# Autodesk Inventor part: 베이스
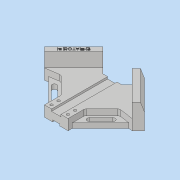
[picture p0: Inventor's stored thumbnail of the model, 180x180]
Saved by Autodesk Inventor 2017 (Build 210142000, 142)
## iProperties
Part Number: 베이스
Material: 일반
Document SubType Name: Modeling
Designer: 00-00
Density: 1 g/cm^3
Appearance: 기본값
Author: 00-00
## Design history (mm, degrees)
sketch "스케치1"
  geometry: L1 (0, 84.853)-(84.853, 0); L2 (84.853, 0)-(0, -84.853); L3 (0, -84.853)-(-84.853, 0); L4 (-84.853, 0)-(0, 84.853); L5 (0, 84.853)-(0, -84.853); L6 (84.853, 0)-(-84.853, 0); L7 (0, 84.853)-(120, 84.853); 1 further point
  constraints: 14 end point, 2 midpoint, 2 parallel, 1 equal length, 1 horizontal, 1 perpendicular
  dimensions: "d0" = 120 distance of L1.start L1.end; "d1" = 45 deg angle of L1 L7; "d2" = 120 distance of L1.end L2.end
extrude "돌출1" new body sketch "스케치1" distance "d3" = 42; taper "d4" = 0 deg
sketch "스케치2"
  geometry: L1 (0, 84.853)-(-84.853, 0) reference; L2 (84.853, 0)-(0, 84.853) reference; L3 (-74.246, -10.607)-(0, 63.64); L4 (0, 63.64)-(74.246, -10.607); L5 (-84.853, 0)-(0, -84.853) reference; L6 (0, -84.853)-(84.853, 0) reference; L7 (-74.246, -10.607)-(0, -84.853); L8 (74.246, -10.607)-(0, -84.853); 1 further point
  constraints: 8 end point, 1 collinear, 1 perpendicular, 1 other
  dimensions: "d5" = 15 distance between parallel lines of L1 L3
extrude "돌출2" cut sketch "스케치2" distance "d6" = 24; taper "d7" = 0 deg
sketch "스케치3"
  geometry: L1 (-20, -64.853)-(20, -64.853); L2 (74.246, -10.607)-(0, -84.853) reference; L3 (0, -84.853)-(-74.246, -10.607) reference; 1 further point
  constraints: 2 end point, 2 point on line, 1 horizontal
  dimensions: "d8" = 20 distance from line of L2.end L1
extrude "돌출3" cut sketch "스케치3" stored distance "d9" = 24; taper "d10" = 0 deg
sketch "스케치4"
  geometry: L1 (-35.355, 49.497)-(-16.005, 30.147); L2 (16.005, 30.147)-(35.355, 49.497); L3 (84.853, 0)-(0, 84.853) reference; L4 (0, 84.853)-(-84.853, 0) reference; L5 (-16.005, 30.147)-(16.005, 30.147); L6 (-20, -64.853)-(20, -64.853) reference; 1 further point
  constraints: 6 end point, 2 parallel, 2 point on line, 1 horizontal
  dimensions: "d11" = 50 distance between parallel lines of L2 L4; "d12" = 50 distance between parallel lines of L3 L1; "d13" = 95 distance between parallel lines of L5 L6
extrude "돌출4" cut sketch "스케치4" stored distance "d14" = 24; taper "d15" = 0 deg
sketch "스케치5"
  geometry: L1 (-5, 42)-(0, 27); L2 (-15, 42)-(0, 42) reference; L3 (0, 0)-(0, 42) reference; 1 further point
  constraints: 2 end point, 2 point on line
  dimensions: "d16" = 5 distance from line of L3 L1.start; "d17" = 15 distance from line of L2 L1.end
extrude "돌출5" cut sketch "스케치5" stored distance "d18" = 24; taper "d19" = 0 deg
sketch "스케치6"
  geometry: L1 (-74.246, -10.607)-(-24.749, 38.891) reference; L2 (-74.246, -10.607)-(-49.497, -7.071); L3 (-49.497, -7.071)-(-20, -36.569); L4 (20, -64.853)-(-20, -64.853) reference; L5 (-20, -36.569)-(-20, -64.853); L6 (-20, -64.853)-(-74.246, -10.607) reference; L7 (-84.853, 0)-(-35.355, 49.497) reference; 1 further point
  constraints: 6 end point
  dimensions: "d20" = 20 distance between parallel lines of L6 L3; "d29" = 30 distance from line of L2.end L7; "d30" = 90 deg angle of L4 L5
extrude "돌출6" cut sketch "스케치6" distance "d21" = 10; taper "d22" = 0 deg
sketch "스케치7"
  geometry: L1 (-68.059, -9.723)-(-20, -57.782); L2 (-20, -64.853)-(-74.246, -10.607) reference; L3 (-74.246, -10.607)-(-49.497, -7.071) reference; L4 (-20, -36.569)-(-20, -64.853) reference; 1 further point
  constraints: 2 end point, 2 point on line, 1 parallel
  dimensions: "d23" = 5 distance between parallel lines of L2 L1
extrude "돌출7" cut sketch "스케치7" stored distance "d24" = 8; taper "d25" = 0 deg
sketch "스케치8"
  geometry: L1 (-49.497, -18.385)-(-29.698, -38.184); L2 (-52.326, -21.213)-(-32.527, -41.012); L3 (-26.87, -35.355)-(-46.669, -15.556); L4 (-68.059, -9.723)-(-20, -57.782) reference; L5 (-84.853, 0)-(-35.355, 49.497) reference; L6 (-81.317, -3.536)-(-74.246, -10.607) reference; A1 r 4 centre (-49.497, -18.385) between (-46.669, -15.556) and (-52.326, -21.213); A2 r 4 centre (-29.698, -38.184) between (-32.527, -41.012) and (-26.87, -35.355); 2 further points
  constraints: 8 end point, 4 point on circle, 4 tangent, 2 centre point, 2 parallel, 1 midpoint
  dimensions: "d27" = 4 radius of A2; "d28" = 38 distance from line of L1.start L5; "d31" = 12 distance from line of L6 point (-39.598, -28.284); "d32" = 28 distance of L2.start L2.end
extrude "돌출8" cut sketch "스케치8" stored distance "d33" = 8; taper "d34" = 0 deg
sketch "스케치9"
  geometry: L1 (-20, 64.853)-(-20, 57.782) reference; L2 (20, 64.853)-(-20, 64.853) reference; 3 further points
  constraints: 1 vertical alignment
  dimensions: "d35" = 6 distance from line of L1 point (-14, 58.853); "d36" = 6 distance from line of L2 point (-14, 58.853); "d37" = 18 distance from line of L2 point (-14, 46.853)
hole "구멍1" sketch "스케치9" at (-14, 46.853), (-14, 58.853) diameter "d38" = 4.5; stored, may be unused: countersink angle "d42" = 90 deg, drill point angle "d44" = 118 deg; dims "d39" = 6, "d40" = 8, "d41" = 10, "d43" = 4
sketch "스케치10"
  geometry: L1 (0, 18)-(40, 18) reference; L2 (40, 0)-(0, 0) reference; L3 (12, 18)-(12, 14.5); L4 (12, 14.5)-(28, 14.5); L5 (36.005, 18)-(36.005, 0) reference; L6 (28, 14.5)-(28, 18); L7 (36.005, 18)-(3.995, 18) reference; L8 (0, 0)-(0, 18) reference; L9 (40, 18)-(40, 0) reference; L10 (3.995, 0)-(36.005, 0) reference; L11 (14, 0)-(14, 3); L12 (14, 3)-(26, 3); L13 (26, 3)-(26, 0); 1 further point
  constraints: 12 end point, 5 perpendicular, 4 point on line, 1 vertical
  dimensions: "d45" = 12 distance between parallel lines of L3 L8; "d47" = 12 distance between parallel lines of L9 L6; "d48" = 3.5 distance between parallel lines of L4 L1; "d49" = 12 distance of L11.end L12.end; "d50" = 14 distance between parallel lines of L8 L11; "d51" = 3 distance between parallel lines of L10 L12
extrude "돌출9" cut sketch "스케치10" stored distance "d52" = 8; taper "d53" = 0 deg
extrude "돌출10" cut sketch "스케치10" stored distance "d54" = 8; taper "d55" = 0 deg
sketch "스케치11"
  geometry: L1 (-74.246, -10.607)-(-24.749, 38.891) reference; L2 (-24.749, 38.891)-(-31.82, 45.962) reference; 2 further points
  constraints: 1 other
  dimensions: "d56" = 5 distance from line of L1 point (-53.033, 17.678); "d57" = 35 distance from line of L2 point (-53.033, 17.678)
feature "엠보싱1" sketch "스케치11" dims "d8" = 20, "d58" = 0.5, "d59" = 0
fillet "모깎기1" dims "d60" = 5
sketch "스케치12"
  geometry: 1 further point
node "솔리드1"
mirror "미러1"
mirror "미러2"
